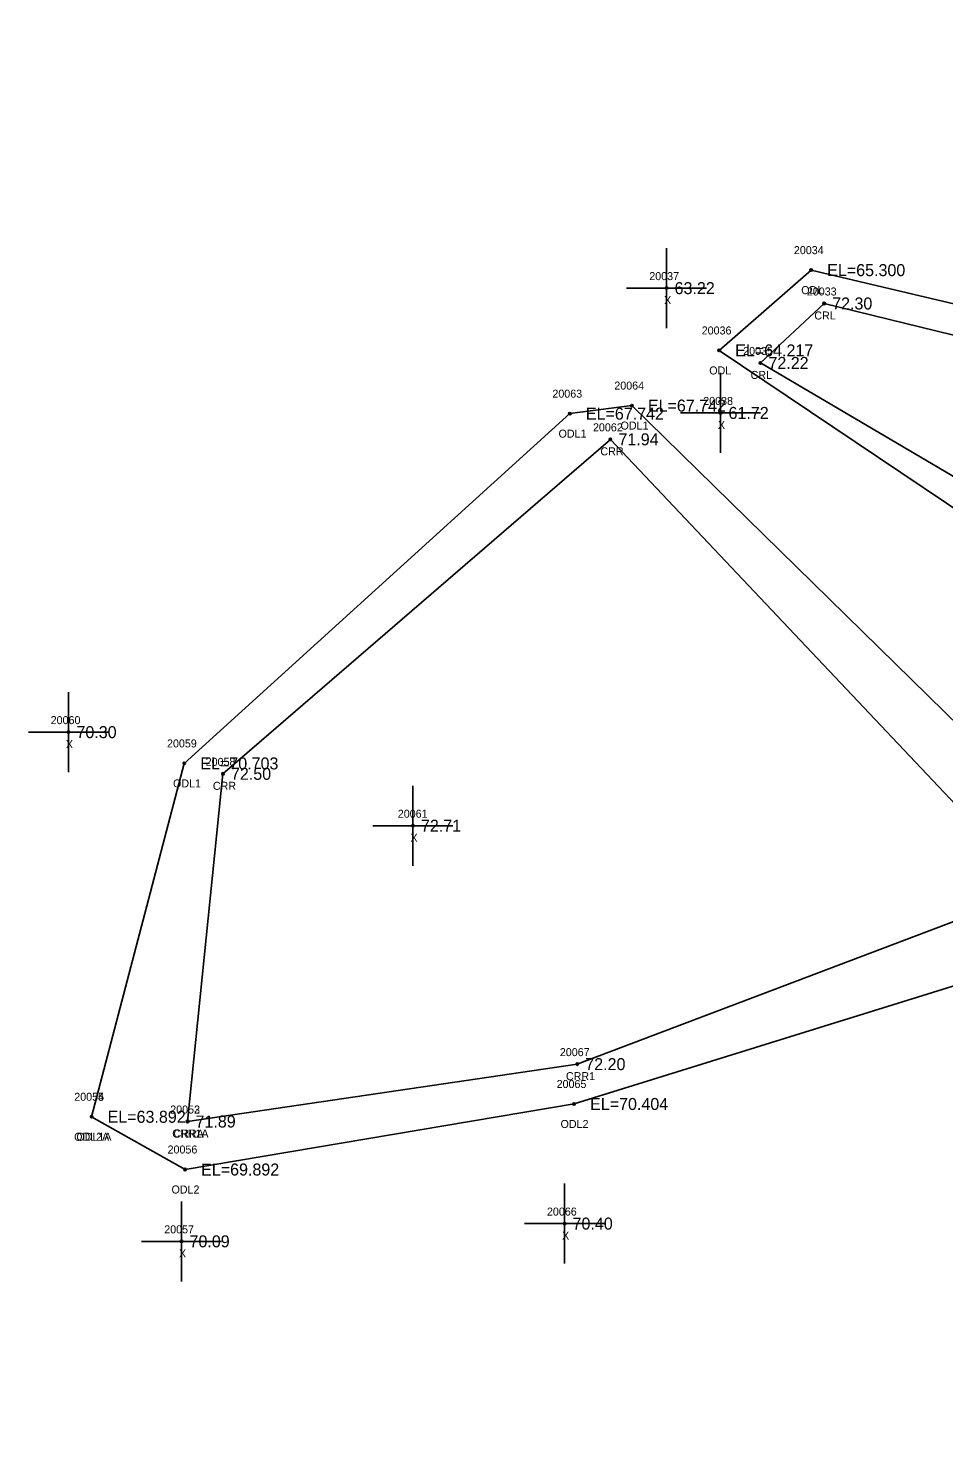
# Model space of a CAD drawing. Extents: x 2505300 to 2506184, y 912965 to 913825.
# Drawn here: x 2505574.8 to 2505689.1, y 913484.8 to 913662.4 of the extents above; entities that cross this region are included whole.
import ezdxf

# ---------------------------------------------------------------- set-up
doc = ezdxf.new("R2010")
doc.units = 0
for name, color, linetype in [('RD_EX_H2O', 7, 'Continuous'), ('RD_EX_H2O_txCode', 7, 'Continuous'), ('RD_EX_Misc', 7, 'Continuous'), ('RD_EX_Misc_txCode', 7, 'Continuous'), ('RD_EX_TX_H2O_ELEV', 7, 'Continuous'), ('RD_EX_TX_Misc_ELEV', 7, 'Continuous'), ('RD_SMD_Locator', 7, 'Continuous')]:
    doc.layers.add(name, color=color, linetype=linetype)

msp = doc.modelspace()

# ---------------------------------------------------------------- linework, layer by layer
at = {"layer": 'RD_EX_H2O'}
for points in [[(2505785.34, 913689.17), (2505760.31, 913663.21), (2505743.1, 913648.56), (2505723.59, 913620.14), (2505672.59, 913632.18), (2505661.09, 913622.14), (2505712.19, 913587.82), (2505787.26, 913549.76), (2505800.1, 913534.14), (2505825.87, 913510.39), (2505850.5, 913511.75), (2505883.26, 913521.88), (2505912.04, 913531.86), (2505948.81, 913534.96), (2505974.98, 913528.19), (2506003.87, 913517.71), (2506051.32, 913503.49), (2506114.3, 913484.75), (2506121.45, 913493.97), (2506156, 913550.08)], [(2505762.26, 913658.11), (2505746.15, 913644.25), (2505726.47, 913615.21), (2505674.21, 913628.01), (2505666.25, 913620.58), (2505714.6, 913592.15), (2505793.9, 913560.45), (2505801.32, 913552.8), (2505803.7, 913539.77), (2505832.63, 913516.96), (2505848.42, 913517.19), (2505881.86, 913528.44), (2505910.2, 913538.78), (2505939.3, 913544.45), (2505946.25, 913542.54), (2505974.65, 913535.18), (2506004.11, 913524.7), (2506052.03, 913515.47), (2506115.49, 913494.68), (2506138.05, 913548.89)], [(2505582.66, 913526.35), (2505594.25, 913570.52), (2505642.43, 913614.24), (2505650.18, 913615.25), (2505697.51, 913568.88), (2505734.95, 913548.51), (2505747.63, 913531.59)], [(2505594.65, 913525.76), (2505599.08, 913569.22), (2505647.5, 913611.03), (2505694.26, 913561.57), (2505732.63, 913542.98), (2505739.24, 913533.06)], [(2505594.65, 913525.76), (2505643.36, 913532.93), (2505701.94, 913555.13), (2505725.91, 913535.7), (2505739.24, 913533.06)], [(2505582.66, 913526.35), (2505594.35, 913519.76), (2505642.96, 913527.95), (2505701.83, 913546.28), (2505723.26, 913530.89), (2505744.8, 913527.51), (2505747.63, 913531.59)]]:
    msp.add_lwpolyline(points, dxfattribs=at)
at = {"layer": 'RD_EX_Misc'}
for p, q in [((2505654.52, 913624.93), (2505654.52, 913634.93)), ((2505649.52, 913629.93), (2505659.52, 913629.93)), ((2505661.26, 913609.33), (2505661.26, 913619.33)), ((2505656.26, 913614.33), (2505666.26, 913614.33)), ((2505579.77, 913569.43), (2505579.77, 913579.43)), ((2505574.77, 913574.43), (2505584.77, 913574.43)), ((2505622.82, 913557.73), (2505622.82, 913567.73)), ((2505617.82, 913562.73), (2505627.82, 913562.73)), ((2505641.77, 913508), (2505641.77, 913518)), ((2505593.9, 913505.78), (2505593.9, 913515.78)), ((2505636.77, 913513), (2505646.77, 913513)), ((2505588.9, 913510.78), (2505598.9, 913510.78))]:
    msp.add_line(p, q, dxfattribs=at)
at = {"layer": 'RD_SMD_Locator'}
for centre in [(2505672.59, 913632.18), (2505654.52, 913629.93), (2505674.21, 913628.01), (2505661.09, 913622.14), (2505666.25, 913620.58), (2505642.43, 913614.24), (2505650.18, 913615.25), (2505661.26, 913614.33), (2505647.5, 913611.03), (2505579.77, 913574.43), (2505594.25, 913570.52), (2505599.08, 913569.22), (2505622.82, 913562.73), (2505643.36, 913532.93), (2505642.96, 913527.95), (2505582.66, 913526.35), (2505582.66, 913526.35), (2505594.65, 913525.76), (2505594.65, 913525.76), (2505594.35, 913519.76), (2505641.77, 913513), (2505593.9, 913510.78)]:
    msp.add_circle(centre, 0.15, dxfattribs=at)

# ---------------------------------------------------------------- texts
at = {"layer": 'RD_EX_H2O_txCode'}
for s, p in [('20034', (2505670.43, 913634.18)), ('ODL', (2505671.35, 913629.18)), ('20033', (2505672.05, 913629.01)), ('CRL', (2505672.98, 913626.01)), ('20036', (2505658.91, 913624.14)), ('20035', (2505664.09, 913621.58)), ('ODL', (2505659.85, 913619.14)), ('CRL', (2505665.02, 913618.58)), ('20064', (2505647.99, 913617.25)), ('20063', (2505640.25, 913616.24)), ('ODL1', (2505641.02, 913611.24)), ('20062', (2505645.32, 913612.03)), ('ODL1', (2505648.77, 913612.25)), ('CRR', (2505646.25, 913609.03)), ('20059', (2505592.09, 913572.52)), ('20058', (2505596.92, 913570.22)), ('ODL1', (2505592.84, 913567.52)), ('CRR', (2505597.82, 913567.22)), ('20067', (2505641.18, 913533.93)), ('20065', (2505640.78, 913529.95)), ('CRR1', (2505641.94, 913530.93)), ('20054', (2505580.5, 913528.35)), ('20055', (2505580.5, 913528.35)), ('20052', (2505592.49, 913526.76)), ('20053', (2505592.49, 913526.76)), ('ODL2', (2505641.27, 913524.95)), ('ODL2A', (2505580.48, 913523.35)), ('ODL1A', (2505580.76, 913523.35)), ('CRR1A', (2505592.74, 913523.76)), ('CRRA', (2505592.9, 913523.76)), ('20056', (2505592.16, 913521.76)), ('ODL2', (2505592.65, 913516.76))]:
    msp.add_text(s, height=1, dxfattribs=at).set_placement(p)
at = {"layer": 'RD_EX_Misc_txCode'}
for s, p in [('20037', (2505652.36, 913630.93)), ('X', (2505654.21, 913627.93)), ('20038', (2505659.1, 913615.33)), ('X', (2505660.94, 913612.33)), ('20060', (2505577.55, 913575.43)), ('X', (2505579.45, 913572.43)), ('20061', (2505620.93, 913563.73)), ('X', (2505622.51, 913560.73)), ('20066', (2505639.57, 913514)), ('20057', (2505591.74, 913511.78)), ('X', (2505641.46, 913511)), ('X', (2505593.58, 913508.78))]:
    msp.add_text(s, height=1, dxfattribs=at).set_placement(p)
at = {"layer": 'RD_EX_TX_H2O_ELEV'}
for s, p in [('EL=65.300', (2505674.59, 913631.43)), ('72.30', (2505675.21, 913627.26)), ('EL=64.217', (2505663.09, 913621.39)), ('72.22', (2505667.25, 913619.83)), ('EL=67.742', (2505652.18, 913614.5)), ('EL=67.742', (2505644.43, 913613.49)), ('71.94', (2505648.5, 913610.28)), ('EL=70.703', (2505596.25, 913569.77)), ('72.50', (2505600.08, 913568.47)), ('72.20', (2505644.36, 913532.18)), ('EL=63.892', (2505584.66, 913525.6)), ('EL=63.892', (2505584.66, 913525.6)), ('EL=70.404', (2505644.96, 913527.2)), ('71.89', (2505595.65, 913525.01)), ('71.89', (2505595.65, 913525.01)), ('EL=69.892', (2505596.35, 913519.01))]:
    msp.add_text(s, height=1.5, dxfattribs=at).set_placement(p)
at = {"layer": 'RD_EX_TX_Misc_ELEV'}
for s, p in [('63.22', (2505655.52, 913629.18)), ('61.72', (2505662.26, 913613.58)), ('70.30', (2505580.77, 913573.68)), ('72.71', (2505623.82, 913561.98)), ('70.40', (2505642.77, 913512.25)), ('70.09', (2505594.9, 913510.03))]:
    msp.add_text(s, height=1.5, dxfattribs=at).set_placement(p)

doc.saveas('drawing.dxf')
